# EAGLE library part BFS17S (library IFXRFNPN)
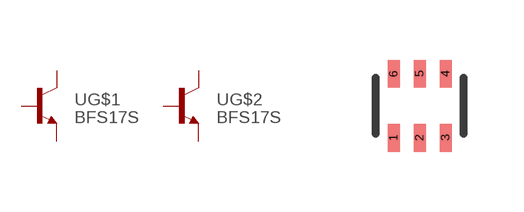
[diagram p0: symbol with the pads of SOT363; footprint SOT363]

Designator prefix -; gates G$1=NPN G$2=NPN

## BFS17S  [SOT363]
1  G$1:B  pas
2  G$1:E  pas
3  G$2:C  pas
4  G$2:B  pas
5  G$2:E  pas
6  G$1:C  pas

## Footprint SOT363 (pad centres in mm)
smd 0.3 x 0.7: 1 -0.65,-0.8; 2 0,-0.8; 3 0.65,-0.8; 4 0.65,0.8; 5 0,0.8; 6 -0.65,0.8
